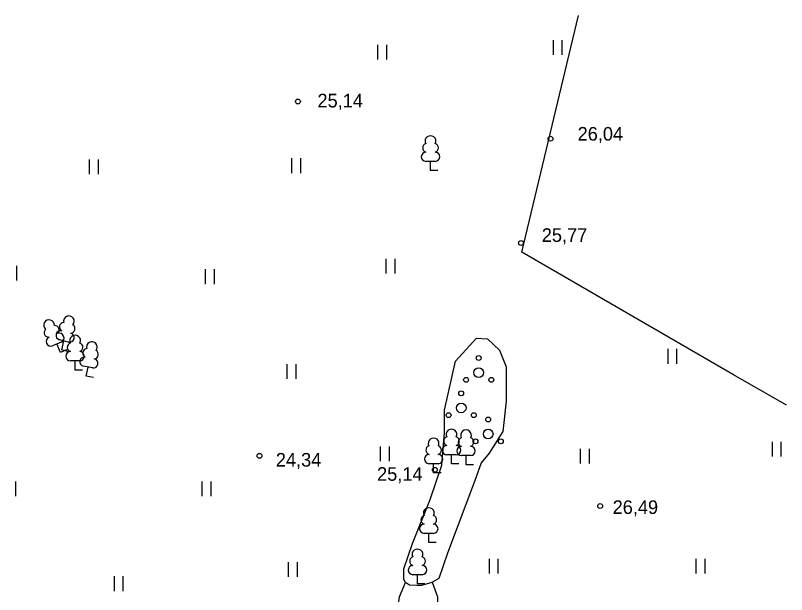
# Model space of a CAD drawing. Extents: x 714391 to 714584, y 6589993 to 6590151.
# Drawn here: x 714544.2 to 714583.92, y 6590121.23 to 6590151.08 of the extents above; entities that cross this region are included whole.
import ezdxf

# ---------------------------------------------------------------- set-up
doc = ezdxf.new("R2010")
doc.units = 0
for name, color, linetype in [('AED', 7, 'Continuous'), ('HALJASTUS', 7, 'Continuous'), ('KORGUS', 7, 'Continuous'), ('PUU', 7, 'Continuous')]:
    doc.layers.add(name, color=color, linetype=linetype)

msp = doc.modelspace()

# ---------------------------------------------------------------- linework, layer by layer
at = {"layer": 'AED'}
msp.add_lwpolyline([(714583.92, 6590130.995), (714581.18, 6590132.55), (714570.29, 6590138.88), (714573.203, 6590151.075)], dxfattribs=at)
at = {"layer": 'HALJASTUS'}
for p, q in [((714571.892, 6590149.801), (714571.892, 6590149.039)), ((714572.348, 6590149.801), (714572.348, 6590149.039)), ((714562.852, 6590149.561), (714562.852, 6590148.799)), ((714563.308, 6590149.561), (714563.308, 6590148.799)), ((714548.002, 6590143.651), (714548.002, 6590142.889)), ((714548.458, 6590143.651), (714548.458, 6590142.889)), ((714558.422, 6590143.711), (714558.422, 6590142.949)), ((714558.878, 6590143.711), (714558.878, 6590142.949)), ((714563.282, 6590138.531), (714563.282, 6590137.769)), ((714563.738, 6590138.531), (714563.738, 6590137.769)), ((714544.248, 6590138.171), (714544.248, 6590137.409)), ((714553.972, 6590137.991), (714553.972, 6590137.229)), ((714554.428, 6590137.991), (714554.428, 6590137.229)), ((714577.802, 6590133.891), (714577.802, 6590133.129)), ((714578.258, 6590133.891), (714578.258, 6590133.129)), ((714558.182, 6590133.111), (714558.182, 6590132.349)), ((714558.638, 6590133.111), (714558.638, 6590132.349)), ((714583.172, 6590129.101), (714583.172, 6590128.339)), ((714583.628, 6590129.101), (714583.628, 6590128.339)), ((714562.992, 6590128.861), (714562.992, 6590128.099)), ((714563.448, 6590128.861), (714563.448, 6590128.099)), ((714573.292, 6590128.741), (714573.292, 6590127.979)), ((714573.748, 6590128.741), (714573.748, 6590127.979)), ((714544.198, 6590127.061), (714544.198, 6590126.299)), ((714553.802, 6590127.061), (714553.802, 6590126.299)), ((714554.258, 6590127.061), (714554.258, 6590126.299)), ((714558.252, 6590122.901), (714558.252, 6590122.139)), ((714558.708, 6590122.901), (714558.708, 6590122.139)), ((714568.592, 6590123.071), (714568.592, 6590122.309)), ((714569.048, 6590123.071), (714569.048, 6590122.309)), ((714579.252, 6590123.071), (714579.252, 6590122.309)), ((714579.708, 6590123.071), (714579.708, 6590122.309)), ((714549.282, 6590122.171), (714549.282, 6590121.409)), ((714549.738, 6590122.171), (714549.738, 6590121.409))]:
    msp.add_line(p, q, dxfattribs=at)
for points in [[(714565.64, 6590121.85), (714565.12, 6590121.69), (714564.88, 6590121.69), (714564.5, 6590121.72), (714564.29, 6590121.86), (714564.2, 6590122.01), (714564.2, 6590122.55), (714564.65, 6590123.86), (714565.56, 6590126.13), (714566.17, 6590127.9), (714566.3, 6590129.59), (714566.3, 6590130.74), (714566.87, 6590133.26), (714567.94, 6590134.45), (714568.52, 6590134.41), (714569.14, 6590133.83), (714569.47, 6590132.97), (714569.47, 6590131.2), (714569.3, 6590129.63), (714568.6, 6590128.52), (714568.19, 6590128.02), (714567.9, 6590127.2), (714566.46, 6590123.37), (714566.01, 6590122.05), (714565.64, 6590121.85)], [(714565.67, 6590121.87), (714565.94, 6590121.11), (714565.97, 6590119.57), (714565.84, 6590118.05), (714565.73, 6590117.28), (714564.97, 6590116.66), (714564.57, 6590116.68), (714564.16, 6590116.97), (714563.71, 6590117.48), (714563.64, 6590118.62), (714563.83, 6590120.02), (714563.98, 6590121.12), (714564.29, 6590121.86)]]:
    msp.add_lwpolyline(points, dxfattribs=at)
for centre, radius in [((714568.06, 6590133.42), 0.125), ((714568.06, 6590132.67), 0.25), ((714567.41, 6590132.295), 0.125), ((714568.71, 6590132.295), 0.125), ((714567.16, 6590131.6), 0.125), ((714567.16, 6590130.85), 0.25), ((714566.51, 6590130.475), 0.125), ((714567.81, 6590130.475), 0.125), ((714568.55, 6590130.25), 0.125), ((714568.55, 6590129.5), 0.25), ((714567.9, 6590129.125), 0.125), ((714569.2, 6590129.125), 0.125)]:
    msp.add_circle(centre, radius, dxfattribs=at)
at = {"layer": 'KORGUS'}
for centre in [(714558.75, 6590146.64), (714571.76, 6590144.72), (714570.24, 6590139.35), (714556.77, 6590128.38), (714565.8, 6590127.66), (714574.32, 6590125.79)]:
    msp.add_circle(centre, 0.125, dxfattribs=at)
at = {"layer": 'PUU'}
for p, q in [((714565.82, 6590143.555), (714565.34, 6590143.555)), ((714565.58, 6590143.08), (714565.58, 6590143.555)), ((714565.96, 6590143.08), (714565.58, 6590143.08)), ((714546.557, 6590134.241), (714546.115, 6590134.055)), ((714546.929, 6590134.241), (714546.464, 6590134.359)), ((714546.58, 6590133.84), (714546.697, 6590134.3)), ((714546.52, 6590133.71), (714546.336, 6590134.148)), ((714546.87, 6590133.857), (714546.52, 6590133.71)), ((714546.948, 6590133.747), (714546.58, 6590133.84)), ((714547.51, 6590133.275), (714547.03, 6590133.275)), ((714547.27, 6590132.8), (714547.27, 6590133.275)), ((714547.65, 6590132.8), (714547.27, 6590132.8)), ((714548.175, 6590132.912), (714547.703, 6590133.002)), ((714547.85, 6590132.49), (714547.939, 6590132.957)), ((714548.223, 6590132.419), (714547.85, 6590132.49)), ((714566.9, 6590128.435), (714566.42, 6590128.435)), ((714566.66, 6590127.96), (714566.66, 6590128.435)), ((714567.65, 6590128.395), (714567.17, 6590128.395)), ((714567.41, 6590127.92), (714567.41, 6590128.395)), ((714565.98, 6590127.975), (714565.5, 6590127.975)), ((714565.74, 6590127.5), (714565.74, 6590127.975)), ((714567.04, 6590127.96), (714566.66, 6590127.96)), ((714567.79, 6590127.92), (714567.41, 6590127.92)), ((714566.12, 6590127.5), (714565.74, 6590127.5)), ((714565.73, 6590124.385), (714565.25, 6590124.385)), ((714565.49, 6590123.91), (714565.49, 6590124.385)), ((714565.87, 6590123.91), (714565.49, 6590123.91)), ((714565.15, 6590122.255), (714564.67, 6590122.255)), ((714564.91, 6590121.78), (714564.91, 6590122.255)), ((714565.29, 6590121.78), (714564.91, 6590121.78))]:
    msp.add_line(p, q, dxfattribs=at)
for centre, radius, start, end in [((714565.58, 6590144.6), 0.277, 332.5799, 207.4201), ((714565.41, 6590144.253), 0.233, 109.0217, 253.1415), ((714565.75, 6590144.253), 0.233, 286.8508, 70.9859), ((714565.343, 6590143.792), 0.238, 90.0016, 269.3953), ((714565.817, 6590143.792), 0.238, 270.6047, 89.9984), ((714546.953, 6590135.313), 0.277, 318.3555, 193.1957), ((714545.931, 6590135.111), 0.277, 355.3729, 230.2131), ((714546.223, 6590134.857), 0.233, 309.6439, 93.7789), ((714546.703, 6590135.018), 0.233, 94.7973, 238.9171), ((714547.033, 6590134.935), 0.233, 272.6264, 56.7615), ((714545.909, 6590134.725), 0.233, 131.8148, 275.9346), ((714546.525, 6590134.589), 0.238, 75.7772, 255.1709), ((714546.463, 6590134.459), 0.238, 293.3977, 112.7914), ((714546.985, 6590134.472), 0.238, 256.3803, 75.774), ((714546.025, 6590134.275), 0.238, 112.7946, 292.1883), ((714547.27, 6590134.32), 0.277, 332.5799, 207.4201), ((714548.134, 6590133.983), 0.277, 321.7956, 196.6358), ((714547.1, 6590133.973), 0.233, 109.0217, 253.1415), ((714547.44, 6590133.973), 0.233, 286.8508, 70.9859), ((714547.902, 6590133.674), 0.233, 98.2374, 242.3573), ((714547.033, 6590133.512), 0.238, 90.0016, 269.3953), ((714547.507, 6590133.512), 0.238, 270.6047, 89.9984), ((714547.75, 6590133.234), 0.238, 79.2173, 258.611), ((714548.236, 6590133.61), 0.233, 276.0665, 60.2016), ((714548.217, 6590133.145), 0.238, 259.8204, 79.2141), ((714566.66, 6590129.48), 0.277, 332.5799, 207.4201), ((714567.41, 6590129.44), 0.277, 332.5799, 207.4201), ((714565.74, 6590129.02), 0.277, 332.5799, 207.4201), ((714566.49, 6590129.133), 0.233, 109.0217, 253.1415), ((714566.83, 6590129.133), 0.233, 286.8508, 70.9859), ((714567.24, 6590129.093), 0.233, 109.0217, 253.1415), ((714567.58, 6590129.093), 0.233, 286.8508, 70.9859), ((714565.57, 6590128.673), 0.233, 109.0217, 253.1415), ((714565.91, 6590128.673), 0.233, 286.8508, 70.9859), ((714566.423, 6590128.672), 0.238, 90.0016, 269.3953), ((714566.897, 6590128.672), 0.238, 270.6047, 89.9984), ((714567.173, 6590128.632), 0.238, 90.0016, 269.3953), ((714567.647, 6590128.632), 0.238, 270.6047, 89.9984), ((714565.503, 6590128.212), 0.238, 90.0016, 269.3953), ((714565.977, 6590128.212), 0.238, 270.6047, 89.9984), ((714565.49, 6590125.43), 0.277, 332.5799, 207.4201), ((714565.32, 6590125.083), 0.233, 109.0217, 253.1415), ((714565.66, 6590125.083), 0.233, 286.8508, 70.9859), ((714565.253, 6590124.622), 0.238, 90.0016, 269.3953), ((714565.727, 6590124.622), 0.238, 270.6047, 89.9984), ((714564.91, 6590123.3), 0.277, 332.5799, 207.4201), ((714564.74, 6590122.953), 0.233, 109.0217, 253.1415), ((714565.08, 6590122.953), 0.233, 286.8508, 70.9859), ((714564.673, 6590122.492), 0.238, 90.0016, 269.3953), ((714565.147, 6590122.492), 0.238, 270.6047, 89.9984)]:
    msp.add_arc(centre, radius, start, end, dxfattribs=at)

# ---------------------------------------------------------------- texts
at = {"layer": 'KORGUS'}
for s, p in [('25,14', (714559.756, 6590146.335)), ('26,04', (714573.156, 6590144.625)), ('25,77', (714571.311, 6590139.405)), ('24,34', (714557.611, 6590127.825)), ('25,14', (714562.826, 6590127.095)), ('26,49', (714574.959, 6590125.385))]:
    msp.add_text(s, height=0.7, dxfattribs=at).set_placement(p)

doc.saveas('drawing.dxf')
